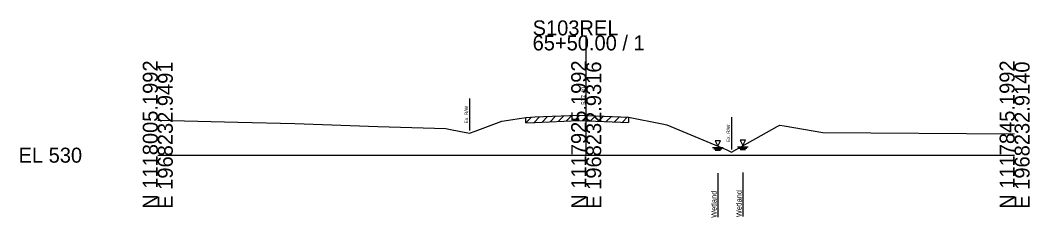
# Model space of a CAD drawing. Extents: x -26 to 163, y -10 to 24518.
# Drawn here: x -25.7 to 162.8, y 13988.3 to 14025.2 of the extents above; entities that cross this region are included whole.
import ezdxf

# ---------------------------------------------------------------- set-up
doc = ezdxf.new("R2010")
doc.units = 0
for name, color, linetype in [('RD_GPK_XS_Cell', 7, 'Continuous'), ('RD_XS_ExGround', 7, 'Continuous'), ('RD_XS_ExPaveRet', 7, 'Continuous'), ('RD_XS_ExRW', 7, 'Continuous'), ('RD_XS_EXWetland', 7, 'Continuous'), ('RD_XS_TX_Elev_EX', 7, 'Continuous')]:
    doc.layers.add(name, color=color, linetype=linetype)

msp = doc.modelspace()

# ---------------------------------------------------------------- linework, layer by layer
at = {"layer": 'RD_GPK_XS_Cell'}
for p, q in [((80, 14000), (80, 14022.36)), ((0, 14000), (80, 14000)), ((80, 14000), (160, 14000))]:
    msp.add_line(p, q, dxfattribs=at)
at = {"layer": 'RD_XS_ExGround'}
msp.add_lwpolyline([(0, 14006.52), (14.92, 14006.18), (25.59, 14005.89), (41.07, 14005.38), (53.79, 14004.97), (54.65, 14004.8), (58.21, 14004.08), (59.25, 14004.47), (64.22, 14006.32), (67.94, 14006.93), (68.75, 14007.06), (70.43, 14007.13), (78.59, 14007.45), (80, 14007.4), (80.32, 14007.39), (87.91, 14007.12), (94.21, 14005.87), (95.08, 14005.68), (106.24, 14000.97), (107.11, 14000.59), (115.69, 14005.36), (116.15, 14005.62), (116.96, 14005.48), (124.18, 14004.24), (160, 14003.96)], dxfattribs=at)
at = {"layer": 'RD_XS_ExPaveRet'}
for p, q in [((68.75, 14006.06), (69.8, 14007.11)), ((68.75, 14006.06), (68.75, 14007.06)), ((68.75, 14006.06), (70.43, 14006.13)), ((70.26, 14006.13), (71.3, 14007.17)), ((70.43, 14006.13), (78.59, 14006.45)), ((71.76, 14006.19), (72.8, 14007.23)), ((73.26, 14006.24), (74.3, 14007.29)), ((74.76, 14006.3), (75.8, 14007.34)), ((76.26, 14006.36), (77.3, 14007.4)), ((77.76, 14006.42), (78.79, 14007.45)), ((78.59, 14006.45), (80, 14006.4)), ((79.26, 14006.43), (80.23, 14007.39)), ((80, 14006.4), (80.32, 14006.39)), ((80.32, 14006.39), (87.91, 14006.12)), ((80.76, 14006.37), (81.73, 14007.34)), ((82.26, 14006.32), (83.23, 14007.29)), ((83.76, 14006.27), (84.73, 14007.24)), ((85.27, 14006.22), (86.23, 14007.18)), ((86.77, 14006.16), (87.73, 14007.13)), ((87.91, 14007.12), (87.91, 14006.12))]:
    msp.add_line(p, q, dxfattribs=at)
at = {"layer": 'RD_XS_ExRW'}
for p, q in [((58.21, 14010.58), (58.21, 14004.58)), ((107.11, 14007.09), (107.11, 14001.09))]:
    msp.add_line(p, q, dxfattribs=at)
at = {"layer": 'RD_XS_EXWetland'}
for p, q in [((104.1, 14002.66), (104.6, 14001.66)), ((105.1, 14002.66), (104.1, 14002.66)), ((104.1, 14002.66), (104.6, 14001.66)), ((105.1, 14002.66), (104.1, 14002.66)), ((104.6, 14001.66), (105.1, 14002.66)), ((104.6, 14001.66), (105.1, 14002.66)), ((108.77, 14002.79), (109.27, 14001.79)), ((109.77, 14002.79), (108.77, 14002.79)), ((108.77, 14002.79), (109.27, 14001.79)), ((109.77, 14002.79), (108.77, 14002.79)), ((109.27, 14001.79), (109.77, 14002.79)), ((109.27, 14001.79), (109.77, 14002.79)), ((103.6, 14001.41), (105.6, 14001.41)), ((103.6, 14001.41), (105.6, 14001.41)), ((103.85, 14001.16), (105.35, 14001.16)), ((103.85, 14001.16), (105.35, 14001.16)), ((104.1, 14000.91), (105.1, 14000.91)), ((104.1, 14000.91), (105.1, 14000.91)), ((108.27, 14001.54), (110.27, 14001.54)), ((108.27, 14001.54), (110.27, 14001.54)), ((108.52, 14001.29), (110.02, 14001.29)), ((108.52, 14001.29), (110.02, 14001.29)), ((108.77, 14001.04), (109.77, 14001.04)), ((108.77, 14001.04), (109.77, 14001.04)), ((104.6, 13996.66), (104.6, 13988.41)), ((104.6, 13996.66), (104.6, 13988.41)), ((109.27, 13996.79), (109.27, 13988.54)), ((109.27, 13996.79), (109.27, 13988.54))]:
    msp.add_line(p, q, dxfattribs=at)

# ---------------------------------------------------------------- texts
at = {"layer": 'RD_GPK_XS_Cell'}
for s, p in [('S103REL', (70, 14022.36)), ('65+50.00 / 1', (70, 14019.56)), ('EL 530', (-26, 13998.6))]:
    msp.add_text(s, height=2.8, dxfattribs=at).set_placement(p)
for s, p in [('N 1118005.1992', (0, 13990)), ('N 1117925.1992', (80, 13990)), ('N 1117845.1992', (160, 13990)), ('E 1968232.9491', (2.8, 13990)), ('E 1968232.9316', (82.8, 13990)), ('E 1968232.9140', (162.8, 13990))]:
    msp.add_text(s, height=2.8, rotation=90, dxfattribs=at).set_placement(p)
at = {"layer": 'RD_XS_ExRW'}
for p in [(57.96, 14005.92), (106.86, 14002.43)]:
    msp.add_text('Ex. R/W ', height=0.65, rotation=90, dxfattribs=at).set_placement(p)
at = {"layer": 'RD_XS_EXWetland'}
for p in [(104.35, 13988.3), (104.35, 13988.3), (109.02, 13988.43), (109.02, 13988.43)]:
    msp.add_text('Wetland ', height=1, rotation=90, dxfattribs=at).set_placement(p)
at = {"layer": 'RD_XS_TX_Elev_EX'}
msp.add_text('537.40', height=0.8, rotation=90, dxfattribs=at).set_placement((79.9, 14009.4))

doc.saveas('drawing.dxf')
